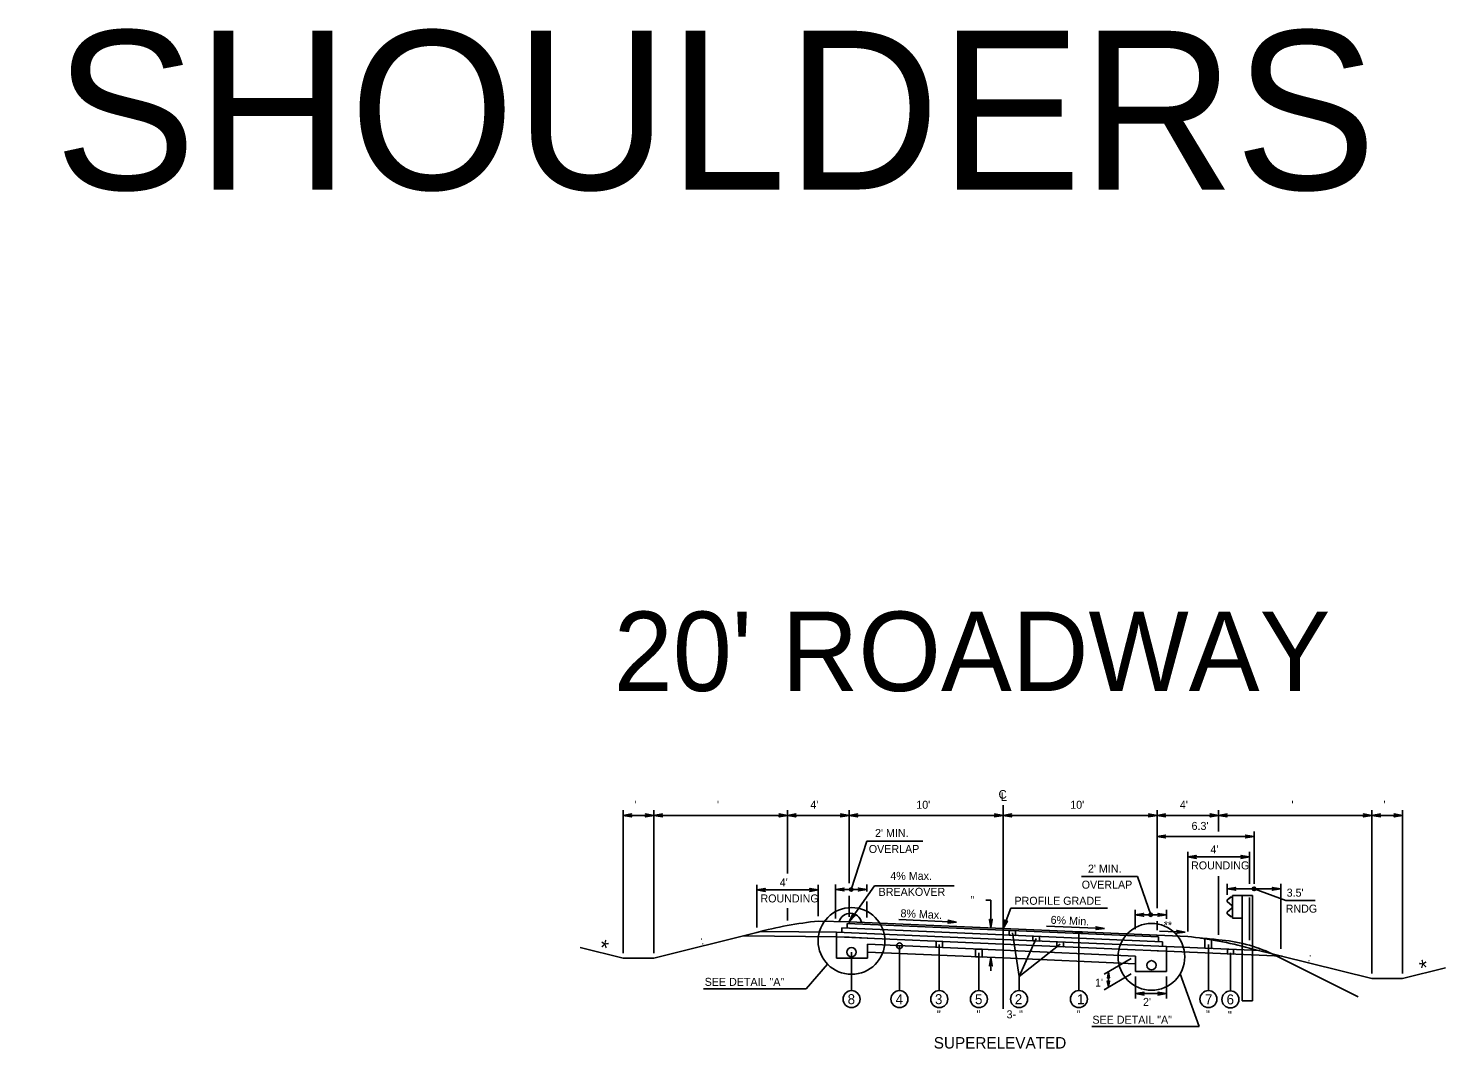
# Model space of a CAD drawing. Extents: x -540 to 1231, y -564 to 421.
# Drawn here: x 411.6 to 659.6, y 242.8 to 421.4 of the extents above; entities that cross this region are included whole.
import ezdxf

# ---------------------------------------------------------------- set-up
doc = ezdxf.new("R2010")
doc.units = 0
doc.layers.add('1', color=7, linetype='Continuous')
doc.layers.add('Des_ Drain_ Ftrs', color=7, linetype='Continuous')

msp = doc.modelspace()

# ---------------------------------------------------------------- linework, layer by layer
at = {"layer": '1'}
for p, q in [((582.17, 249.77), (582.17, 285.42)), ((515.69, 259.52), (515.69, 284.54)), ((521.08, 283.66), (515.69, 283.66)), ((521.08, 259.52), (521.08, 284.54)), ((544.46, 283.66), (521.08, 283.66)), ((544.46, 273.46), (544.46, 284.54)), ((555.23, 283.66), (544.46, 283.66)), ((555.23, 271.81), (555.23, 284.54)), ((582.17, 283.66), (555.23, 283.66)), ((582.17, 283.66), (609.12, 283.66)), ((609.12, 267.39), (609.12, 284.54)), ((609.12, 283.66), (619.89, 283.66)), ((619.89, 280.84), (619.89, 284.54)), ((619.89, 283.66), (646.71, 283.66)), ((646.71, 255.96), (646.71, 284.54)), ((646.71, 283.66), (652.1, 283.66)), ((652.1, 255.96), (652.1, 284.54)), ((626.09, 271.68), (626.09, 280.84)), ((555.6, 270.68), (558.35, 279.17)), ((568.11, 279.17), (558.35, 279.17)), ((609.11, 279.96), (626.09, 279.96)), ((614.5, 263.33), (614.5, 277.26)), ((614.5, 276.38), (625.28, 276.38)), ((625.28, 271.68), (625.28, 277.26)), ((595.91, 272.93), (605.68, 272.93)), ((608.01, 266.26), (605.68, 272.93)), ((619.89, 262.77), (619.89, 273.02)), ((539.07, 264.02), (539.07, 271.48)), ((549.84, 270.6), (539.07, 270.6)), ((549.84, 266.03), (549.84, 271.48)), ((552.86, 265.62), (552.86, 271.56)), ((558.34, 270.68), (552.86, 270.68)), ((555.23, 265.04), (559.65, 271.34)), ((558.34, 270.35), (558.34, 271.56)), ((573.6, 271.34), (559.65, 271.34)), ((621.39, 269.73), (621.39, 271.68)), ((621.39, 270.8), (630.78, 270.8)), ((626.09, 270.8), (631.64, 268.73)), ((630.78, 260.32), (630.78, 271.68)), ((555.23, 265.92), (555.23, 269.56)), ((558.34, 265.78), (558.34, 268.59)), ((580.04, 268.83), (579.16, 268.83)), ((580.04, 268.83), (580.04, 263.95)), ((621.46, 268.51), (622.19, 267.87)), ((621.99, 269.33), (621.48, 268.94)), ((621.48, 268.53), (622.21, 267.9)), ((622, 269.3), (621.49, 268.92)), ((622.31, 269.39), (621.99, 269.33)), ((622.31, 269.36), (622, 269.3)), ((622.31, 269.62), (622.31, 265.68)), ((622.31, 269.62), (623.99, 269.62)), ((623.99, 269.62), (623.99, 251.22)), ((625.82, 269.62), (623.99, 269.62)), ((625.28, 261.8), (625.28, 269.3)), ((625.82, 269.62), (625.82, 251.22)), ((631.64, 268.73), (636.8, 268.73)), ((544.46, 265.26), (544.46, 267.44)), ((563.92, 265.42), (574.04, 264.98)), ((582.18, 263.85), (583.56, 267.43)), ((600.48, 267.43), (583.56, 267.43)), ((605.27, 263.73), (605.27, 267.14)), ((605.27, 266.26), (610.76, 266.26)), ((610.76, 265.57), (610.76, 267.14)), ((622.19, 267.42), (621.46, 266.79)), ((622.21, 267.4), (621.48, 266.77)), ((621.48, 266.36), (621.99, 265.97)), ((621.49, 266.38), (622, 266)), ((621.99, 265.97), (622.31, 265.91)), ((622, 266), (622.31, 265.94)), ((622.28, 267.69), (622.28, 267.61)), ((622.31, 267.69), (622.31, 267.61)), ((622.31, 265.68), (623.99, 265.68)), ((539.07, 263.14), (521.08, 258.64)), ((539.82, 263.34), (553.04, 263.21)), ((555.23, 265.04), (549.84, 265.15)), ((582.17, 261.94), (553.04, 263.21)), ((553.04, 262.41), (553.04, 263.21)), ((582.17, 262.75), (553.96, 263.98)), ((553.96, 263.17), (553.96, 263.98)), ((582.17, 263.56), (554.89, 264.75)), ((554.89, 263.94), (554.89, 264.75)), ((582.17, 263.86), (555.23, 265.04)), ((555.23, 264.74), (555.23, 265.04)), ((609.12, 262.68), (582.17, 263.86)), ((609.35, 262.37), (582.17, 263.56)), ((583.81, 263.08), (584.97, 255.46)), ((589.8, 264.29), (599.91, 263.85)), ((595.44, 263.12), (595.44, 252.97)), ((609.12, 263.56), (609.12, 265.13)), ((614.05, 263.21), (609.56, 263.41)), ((508.16, 260.53), (515.69, 258.64)), ((536.76, 262.57), (553.04, 262.41)), ((553.04, 258.65), (553.04, 262.4)), ((553.04, 262.4), (555.23, 262.31)), ((582.17, 261.13), (553.06, 262.4)), ((555.23, 262.31), (558.53, 262.16)), ((582.17, 260.05), (558.43, 261.09)), ((558.43, 258.65), (558.43, 261.09)), ((564.05, 260.84), (564.05, 252.97)), ((571.02, 261.08), (571.02, 252.97)), ((610.06, 261.53), (582.17, 262.75)), ((610.76, 260.69), (582.17, 261.94)), ((605.28, 260.12), (582.17, 261.13)), ((587.99, 262.1), (584.97, 255.46)), ((592.16, 261.09), (584.97, 255.46)), ((614.49, 262.45), (609.12, 262.68)), ((609.12, 262.38), (609.12, 262.68)), ((609.35, 262.37), (609.35, 261.56)), ((610.06, 261.53), (610.06, 260.72)), ((610.76, 260.69), (610.76, 259.88)), ((627.1, 259.98), (610.76, 260.69)), ((618.11, 261.07), (618.11, 252.97)), ((621.39, 261.67), (621.39, 261.67)), ((625.27, 260.44), (646.7, 255.08)), ((521.08, 258.64), (515.69, 258.64)), ((558.43, 258.65), (553.04, 258.65)), ((555.66, 259.95), (555.66, 259.95)), ((555.66, 259.72), (555.66, 252.97)), ((582.17, 258.71), (558.43, 259.74)), ((577.95, 259.57), (577.95, 252.97)), ((580.04, 258.8), (580.04, 256.43)), ((605.37, 259.04), (582.17, 260.05)), ((605.37, 257.69), (582.17, 258.71)), ((604.61, 258.6), (599.85, 255.85)), ((610.76, 259.88), (605.28, 260.12)), ((605.37, 256.35), (605.37, 259.04)), ((605.37, 259.04), (605.37, 259.04)), ((610.77, 259.88), (609.12, 259.96)), ((610.76, 256.35), (610.76, 259.88)), ((631.02, 259), (610.76, 259.88)), ((621.95, 259.6), (621.95, 252.97)), ((629.28, 259.44), (644.33, 251.91)), ((547.7, 253.31), (551.44, 257.63)), ((584.97, 255.46), (584.97, 252.97)), ((604.61, 255.91), (599.84, 253.15)), ((600.62, 256.29), (600.6, 253.59)), ((605.37, 256.35), (610.76, 256.35)), ((605.37, 255.47), (605.37, 251.58)), ((610.76, 255.47), (610.76, 251.58)), ((613.17, 255.95), (616.5, 246.68)), ((659.62, 256.96), (652.09, 255.08)), ((529.77, 253.31), (547.7, 253.31)), ((646.7, 255.08), (652.09, 255.08)), ((605.37, 252.46), (610.76, 252.46)), ((625.82, 251.22), (623.99, 251.22)), ((597.71, 246.68), (616.5, 246.68))]:
    msp.add_line(p, q, dxfattribs=at)
for points in [[(583.24, 263.51), (584.38, 263.46), (584.38, 262.65), (583.24, 262.7)], [(594.86, 263.3), (596.01, 263.25), (596.01, 262.96), (594.86, 263.01)], [(570.45, 261.64), (571.59, 261.59), (571.59, 260.52), (570.45, 260.57)], [(587.41, 262.52), (588.56, 262.47), (588.56, 261.66), (587.41, 261.71)], [(591.59, 261.53), (592.73, 261.48), (592.73, 260.67), (591.59, 260.72)], [(618.66, 260.34), (617.5, 260.39), (617.5, 262.07), (618.66, 261.88)], [(577.38, 260.26), (578.52, 260.21), (578.52, 258.86), (577.38, 258.91)], [(621.44, 260.23), (622.49, 260.18), (622.49, 259.37), (621.44, 259.42)]]:
    msp.add_lwpolyline(points, close=True, dxfattribs=at)
for centre, radius in [((555.6, 270.68), 0.3), ((626.09, 270.8), 0.3), ((555.65, 261.68), 5.84), ((608.01, 266.26), 0.3), ((608.14, 258.9), 5.84), ((555.66, 259.72), 0.808), ((564.05, 260.84), 0.5), ((608.15, 257.42), 0.808), ((555.66, 251.49), 1.49), ((564.05, 251.49), 1.49), ((571.02, 251.49), 1.49), ((577.95, 251.49), 1.49), ((584.97, 251.49), 1.49), ((595.44, 251.49), 1.49), ((618.11, 251.49), 1.49), ((621.95, 251.44), 1.49)]:
    msp.add_circle(centre, radius, dxfattribs=at)
for centre, radius, start, end in [((621.64, 268.72), 0.278, 126.9799, 229.021), ((621.64, 268.72), 0.249, 126.9799, 229.021), ((622.03, 267.69), 0.249, 0, 49.0365), ((622.03, 267.69), 0.278, 0, 49.0365), ((555.44, 264.52), 2, 12.2495, 163.8033), ((621.64, 266.58), 0.278, 130.979, 233.0201), ((621.64, 266.58), 0.249, 130.979, 233.0201), ((622.03, 267.61), 0.249, 310.9635, 0), ((622.03, 267.61), 0.278, 310.9635, 0), ((556.74, 198.32), 67.19, 95.8901, 105.2487), ((607.61, 195.61), 67.19, 74.7593, 84.1179), ((609.07, 161.23), 101.24, 83.8633, 85.6775), ((617.77, 234.6), 27.37, 65.1374, 85.5513)]:
    msp.add_arc(centre, radius, start, end, dxfattribs=at)
at = {"layer": 'Des_ Drain_ Ftrs'}
for points in [[(515.69, 283.66), (517.18, 283.41), (516.88, 283.66), (517.18, 283.91)], [(521.08, 283.66), (519.59, 283.41), (519.88, 283.66), (519.59, 283.91)], [(521.08, 283.66), (522.57, 283.41), (522.27, 283.66), (522.57, 283.91)], [(544.46, 283.66), (542.97, 283.41), (543.26, 283.66), (542.97, 283.91)], [(544.46, 283.66), (545.94, 283.41), (545.65, 283.66), (545.94, 283.91)], [(555.23, 283.66), (553.74, 283.41), (554.04, 283.66), (553.74, 283.91)], [(555.23, 283.66), (556.72, 283.41), (556.43, 283.66), (556.72, 283.91)], [(582.17, 283.66), (580.69, 283.41), (580.98, 283.66), (580.69, 283.91)], [(582.17, 283.66), (583.66, 283.41), (583.37, 283.66), (583.66, 283.91)], [(609.12, 283.66), (607.63, 283.41), (607.92, 283.66), (607.63, 283.91)], [(609.12, 283.66), (610.6, 283.41), (610.31, 283.66), (610.6, 283.91)], [(619.89, 283.66), (618.4, 283.41), (618.7, 283.66), (618.4, 283.91)], [(619.89, 283.66), (621.38, 283.41), (621.08, 283.66), (621.38, 283.91)], [(646.71, 283.66), (645.22, 283.41), (645.52, 283.66), (645.22, 283.91)], [(646.71, 283.66), (648.2, 283.41), (647.91, 283.66), (648.2, 283.91)], [(652.1, 283.66), (650.61, 283.41), (650.91, 283.66), (650.61, 283.91)], [(609.11, 279.96), (610.6, 279.71), (610.31, 279.96), (610.6, 280.2)], [(626.09, 279.96), (624.6, 279.71), (624.89, 279.96), (624.6, 280.2)], [(614.5, 276.38), (615.99, 276.13), (615.7, 276.38), (615.99, 276.63)], [(625.28, 276.38), (623.79, 276.13), (624.09, 276.38), (623.79, 276.63)], [(539.07, 270.6), (540.56, 270.35), (540.26, 270.6), (540.56, 270.85)], [(549.84, 270.6), (548.36, 270.35), (548.65, 270.6), (548.36, 270.85)], [(552.86, 270.68), (554.35, 270.44), (554.05, 270.68), (554.35, 270.93)], [(558.34, 270.68), (556.85, 270.44), (557.15, 270.68), (556.85, 270.93)], [(621.39, 270.8), (622.88, 270.55), (622.59, 270.8), (622.88, 271.05)], [(630.78, 270.8), (629.29, 270.55), (629.59, 270.8), (629.29, 271.05)], [(555.23, 265.04), (556.29, 266.11), (555.91, 266.01), (555.88, 266.4)], [(580.04, 263.95), (580.29, 265.44), (580.04, 265.15), (579.79, 265.44)], [(605.27, 266.26), (606.76, 266.01), (606.46, 266.26), (606.76, 266.51)], [(610.76, 266.26), (609.27, 266.01), (609.56, 266.26), (609.27, 266.51)], [(574.04, 264.98), (572.54, 264.8), (572.84, 265.03), (572.56, 265.29)], [(582.18, 263.85), (582.95, 265.15), (582.61, 264.97), (582.48, 265.33)], [(599.91, 263.85), (598.41, 263.67), (598.72, 263.9), (598.43, 264.16)], [(614.05, 263.21), (612.56, 263.03), (612.86, 263.26), (612.58, 263.52)], [(580.04, 258.8), (580.29, 257.31), (580.04, 257.61), (579.79, 257.31)], [(600.62, 256.29), (600.43, 255.21), (600.61, 255.42), (600.79, 255.21)], [(600.6, 253.59), (600.42, 254.67), (600.6, 254.46), (600.78, 254.67)], [(605.37, 252.46), (606.86, 252.21), (606.57, 252.46), (606.86, 252.71)], [(610.76, 252.46), (609.27, 252.21), (609.57, 252.46), (609.27, 252.71)]]:
    msp.add_lwpolyline(points, close=True, dxfattribs=at)

# ---------------------------------------------------------------- texts
at = {"layer": '1'}
for s, height, p in [('COLLECTORS WITHOUT PAVED SHOULDERS', 27.7958, (-166.21, 393.19)), ("20' ROADWAY", 13.8979, (514.05, 305.42)), (" '", 1.4, (517.19, 284.81)), ("  '", 1.4, (531.07, 284.81)), ("4'", 1.4, (548.45, 284.81)), ("10'", 1.4, (566.99, 284.81)), ("10'", 1.4, (593.93, 284.81)), ("4'", 1.4, (613.11, 284.81)), ("  '", 1.4, (631.61, 284.81)), (" '", 1.4, (648.21, 284.81)), ("2' MIN.", 1.4, (559.77, 279.87)), ("6.3'", 1.4, (615.16, 281.11)), ('OVERLAP', 1.4, (558.68, 277.07)), ("4'", 1.4, (618.46, 277)), ('ROUNDING', 1.4, (615.07, 274.2)), ('4% Max.', 1.4, (562.45, 272.37)), ("2' MIN.", 1.4, (597.03, 273.63)), ("4'", 1.4, (543.1, 271.22)), ('BREAKOVER', 1.4, (560.4, 269.57)), ('OVERLAP', 1.4, (595.94, 270.83)), ("3.5'", 1.4, (631.8, 269.43)), ('ROUNDING', 1.4, (539.72, 268.42)), ('PROFILE GRADE', 1.4, (584.17, 268.01)), ('RNDG', 1.4, (631.63, 266.63)), ('SEE DETAIL "A"', 1.4, (529.96, 253.82)), ('8', 1.75, (554.98, 250.61)), ('4', 1.75, (563.38, 250.61)), ('3', 1.75, (570.26, 250.61)), ('5', 1.75, (577.26, 250.61)), ('2', 1.75, (584.23, 250.61)), ('1', 1.75, (595.13, 250.61)), ("2'", 1.4, (606.66, 250.31)), ('7', 1.75, (617.52, 250.61)), ('6', 1.75, (621.29, 250.57)), (' "', 1.4, (570.08, 248.13)), (' "', 1.4, (577.01, 248.13)), ('3- "', 1.4, (582.79, 248.13)), (' "', 1.4, (594.49, 248.13)), ('SEE DETAIL "A"', 1.4, (597.81, 247.19)), (' "', 1.4, (617.17, 248.13)), (' "', 1.4, (621.01, 247.99)), ('SUPERELEVATED', 2, (570.05, 242.85))]:
    msp.add_text(s, height=height, dxfattribs=at).set_placement(p)
for s, height, rotation, p in [('  "', 1.4, 0.1438, (575.43, 268.13)), ('8% Max.', 1.4, 357.3761, (564.2, 265.84)), ('6% Min.', 1.4, 357.373, (590.47, 264.69)), ('**', 1.4, 357.2162, (610.24, 263.77)), ('*', 2.8, 347.1521, (511.32, 259.29)), (' : ', 1.4, 14.2282, (528.89, 260.88)), (' : ', 1.4, 345.7718, (634.93, 258.31)), ('*', 2.8, 12.8479, (655.4, 255.48)), ("1'", 1.4, 0.1438, (598.27, 253.68))]:
    msp.add_text(s, height=height, rotation=rotation, dxfattribs=at).set_placement(p)
at = {"layer": 'Des_ Drain_ Ftrs'}
for s, p in [('C', (581.38, 286.58)), ('L', (581.77, 286.18))]:
    msp.add_text(s, height=1.5, dxfattribs=at).set_placement(p)

doc.saveas('drawing.dxf')
